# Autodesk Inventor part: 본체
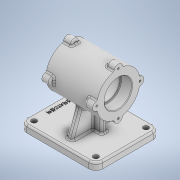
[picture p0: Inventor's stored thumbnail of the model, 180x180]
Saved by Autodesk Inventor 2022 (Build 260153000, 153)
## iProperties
Created: 2023-05
Part Number: 본체
Material: 일반
Document SubType Name: Modeling
Designer: Admin
Density: 1 g/cm^3
Appearance: 기본값
Author: Admin
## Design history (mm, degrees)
sketch "스케치1"
  geometry: L1 (-78.381, 0)-(72.862, 0) reference; L2 (0, -7.4)-(0, 44.4) reference; L3 (-56.775, 0)-(51.256, 0); L4 (-43.5, 0)-(-43.5, 37); L5 (-43.5, 37)-(43.5, 37); L6 (43.5, 37)-(43.5, 0); 1 further point
  constraints: 8 end point, 4 point on line, 3 perpendicular, 1 other
  dimensions: "d0" = 74 diameter of L5 L3; "d1" = 87 distance of L4.end L5.end
revolve "회전1" sketch "스케치1" stored, may be unused: angle "d2" = 90 deg
node "작업 평면1"
sketch "스케치3"
  geometry: L1 (70, 55)-(-60, 55); L2 (-60, 55)-(-60, -55); L3 (-60, -55)-(70, -55); L4 (70, -55)-(70, 55); L5 (0, -77)-(0, 77) reference; L6 (96, 0)-(-86, 0) reference; 1 further point
  constraints: 8 end point, 2 parallel, 1 horizontal, 1 perpendicular
  dimensions: "d11" = 130 distance of L1.start L1.end; "d12" = 110 distance of L3.end L1.start; "d13" = 70 distance between parallel lines of L5 L4; "d14" = 55 distance between parallel lines of L6 L1
extrude "돌출2" join sketch "스케치3" distance "d15" = 12; taper "d16" = 0 deg
sketch "스케치4"
  geometry: L1 (-20, -27.453)-(-20, -74.651); L2 (-20, -74.651)-(20, -74.651); L3 (20, -74.651)-(20, -27.453); L4 (20, -27.453)-(-20, -27.453); L5 (0, -89.581)-(0, 14.93) reference; L6 (-28, 0)-(28, 0) reference; 1 further point
  constraints: 8 end point, 1 horizontal, 1 parallel, 1 perpendicular, 1 vertical, 1 other
  dimensions: "d17" = 40 distance of L3.end L1.start; "d18" = 47.19748 distance between parallel lines of L2 L4; "d19" = 27.45319 distance between parallel lines of L6 L4
extrude "돌출3" join sketch "스케치4" stored distance "d20" = 10; taper "d21" = 0 deg
sketch "스케치5"
  geometry: L1 (-24.719, -24.519)-(-70, -41); L2 (-70, -41)-(-70, 41); L3 (-70, 41)-(-24.719, 24.519); L4 (-24.719, 24.519)-(-24.719, -24.519); L5 (-70, 55)-(-70, -55) reference; L6 (-84, 0)-(14, 0) reference; L7 (0, -77)-(0, 77) reference; L8 (-82, 77)-(-82, -77) reference; 1 further point
  constraints: 8 end point, 1 parallel, 1 vertical
  dimensions: "d22" = 110 deg angle of L5 L3; "d23" = 110 deg angle of L5 L1; "d24" = 82 distance of L1.end L2.end; "d25" = 41 distance from line of L6 L2.end; "d26" = 45.28124 distance between parallel lines of L5 L4; "d27" = 12 distance between parallel lines of L8 L2
extrude "돌출4" join sketch "스케치5" stored distance "d28" = 10; taper "d29" = 0 deg
sketch "스케치6"
  geometry: L1 (-81.048, 0)-(86.657, 0); L2 (-114.589, 0)-(120.198, 0) reference; L3 (0, -105.8)-(0, 60.8) reference; L4 (-43.5, -37)-(-43.5, 37) reference; L5 (-43.5, 23.5)-(-25.5, 23.5); L6 (-24.5, 22.5)-(-24.5, 21); L7 (-24.5, 21)-(24.5, 21); L8 (24.5, 21)-(24.5, 22.5); L9 (25.5, 23.5)-(43.5, 23.5); L10 (43.5, -37)-(43.5, 37) reference; A1 r 1 centre (-25.5, 22.5) between (-24.5, 22.5) and (-25.5, 23.5); A2 r 1 centre (25.5, 22.5) between (25.5, 23.5) and (24.5, 22.5); 4 further points
  constraints: 12 end point, 6 point on line, 4 point on circle, 4 tangent, 3 horizontal, 3 perpendicular, 2 centre point, 1 equal radius, 1 other
  dimensions: "d32" = 47 diameter of L9 L1; "d33" = 42 diameter of L7 L1; "d34" = 49 distance between parallel lines of L8 L6; "d35" = 1 radius of A1
revolve "회전2" sketch "스케치6" stored, may be unused: angle "d36" = 90 deg
chamfer "모따기1" distance "d37" = 1; stored, may be unused: second distance "d38" = 2, angle "d39" = 45 deg
sketch "스케치8"
  geometry: L1 (0, -105.8)-(0, 60.8) reference; L2 (-77, 0)-(77, 0) reference; C1 r 37 at (0, 0); C2 r 7 at (0, 37); C3 r 7 at (-37, 0); C4 r 7 at (0, -37); C5 r 7 at (37, 0); 1 further point
  constraints: 5 centre point, 1 coincident, 1 point on line, 9 other
  dimensions: "d40" = 74 diameter of C1; "d41" = 14 diameter of C2; "d42" = 37 distance of point (0, 0) C2.centre; "d45" = 360 deg dimension on point (0, 0) C2.centre (derived)
extrude "돌출5" join sketch "스케치8" distance "d47" = 14; taper "d48" = 0 deg
sketch "스케치9"
  geometry: A1 r 7 centre (-37, 37) between (-30.031, 36.338) and (-43.969, 36.338) reference; A2 r 7 centre (0, 0) between (-0.662, -6.969) and (-0.662, 6.969) reference; A3 r 7 centre (-37, -37) between (-43.969, -36.338) and (-30.031, -36.338) reference; A4 r 7 centre (-74, 0) between (-73.338, 6.969) and (-73.338, -6.969) reference; 5 further points
  constraints: 4 coincident
hole "구멍1" sketch "스케치9" at (-37, 37), (0, 0), (-37, -37), (-74, 0) diameter "d49" = 3.242; stored, may be unused: countersink angle "d53" = 90 deg, drill point angle "d55" = 118 deg; dims "d50" = 8, "d51" = 4, "d52" = 2, "d54" = 10
fillet "모깎기1" dims "d56" = 3
fillet "모깎기2" dims "d57" = 3
fillet "모깎기3" dims "d58" = 12
sketch "스케치10"
  geometry: A1 r 12 centre (-58, 43) between (-58, 55) and (-70, 43) reference; A2 r 12 centre (-58, -43) between (-70, -43) and (-58, -55) reference; A3 r 12 centre (48, -43) between (48, -55) and (60, -43) reference; A4 r 12 centre (48, 43) between (60, 43) and (48, 55) reference; 5 further points
  constraints: 4 coincident
hole "구멍2" sketch "스케치10" at (-58, 43), (-58, -43), (48, -43), (48, 43) diameter "d59" = 9; stored, may be unused: countersink angle "d63" = 90 deg, drill point angle "d65" = 0 deg; dims "d60" = 8, "d61" = 4, "d62" = 2, "d64" = 12
fillet "모깎기4" dims "d66" = 3
sketch "스케치11"
  geometry: L1 (-96, 0)-(86, 0) reference; L2 (0, 77)-(0, -77) reference; 2 further points
  constraints: 1 point on line, 1 other
  dimensions: "d67" = 58 distance from line of L2 point (-58, 0)
feature "엠보싱1" sketch "스케치11" dims "d0" = 74, "d1" = 87, "d17" = 40, "d18" = 47.19748, "d19" = 27.45319, "d68" = 0.5, "d69" = 0
node "솔리드1"
mirror "미러2"
mirror "미러3"
feature "A9D066F2-1C7D-4E18-AEED-F7BC21143FA4" dims "d59" = 9, "d60" = 8, "d61" = 4, "d62" = 2, "d63" = 90 deg, "d64" = 12, "d65" = 0
other parameters: "d10" = -82
